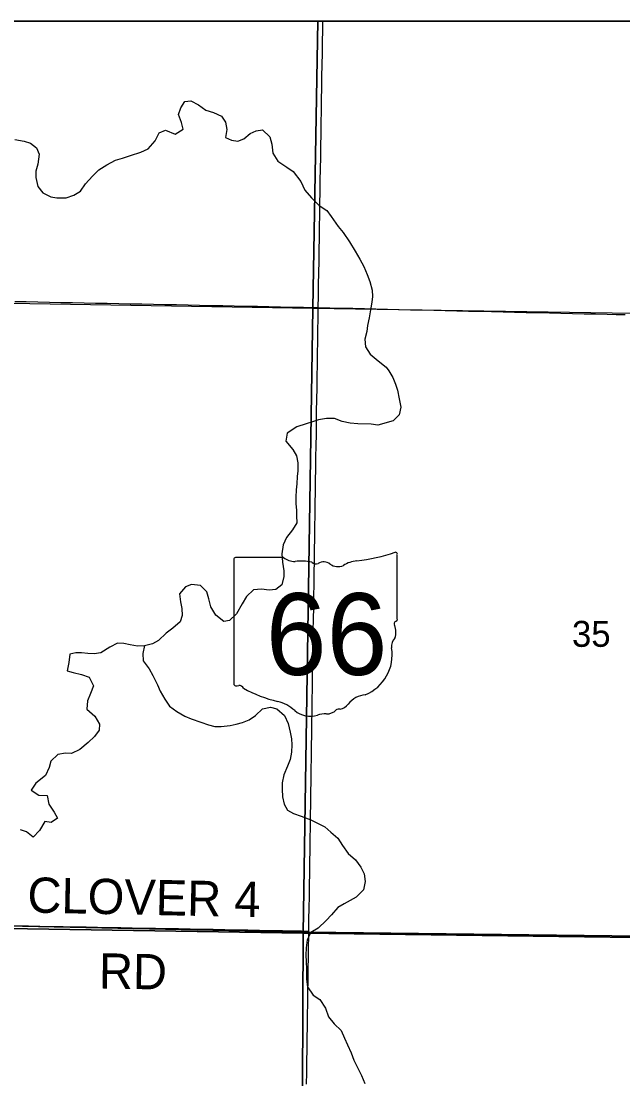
# Model space of a CAD drawing. Extents: x 0 to 34, y 0 to 22.
# Drawn here: x 5.346 to 6.316, y 19.194 to 20.9 of the extents above; entities that cross this region are included whole.
import ezdxf

# ---------------------------------------------------------------- set-up
doc = ezdxf.new("R2010")
doc.units = 0
for name, color, linetype in [('GM_X_Corporation', 7, 'Continuous'), ('GM_X_Minor_River', 7, 'Continuous'), ('GM_X_Section_Text', 7, 'Continuous'), ('GM_X_State_Location', 7, 'Continuous'), ('GM_X_State_Route', 7, 'Continuous'), ('GM_X_State_Shield', 7, 'Continuous'), ('GM_X_Township_Road', 7, 'Continuous'), ('GM_X_Township_Road_Text', 7, 'Continuous'), ('SH_Data', 7, 'Continuous')]:
    doc.layers.add(name, color=color, linetype=linetype)

msp = doc.modelspace()

# ---------------------------------------------------------------- linework, layer by layer
at = {"layer": 'GM_X_Corporation'}
for points in [[(8.9, 20.9), (2.1, 20.9)], [(7.8362, 20.9), (2.1, 20.9)], [(4.7562, 19.4505), (4.8049, 19.4497), (5.2195, 19.4431), (5.8089, 19.4308), (6.6989, 19.42)], [(7.8062, 19.1933), (7.8077, 19.2659), (7.8087, 19.3138), (7.8096, 19.3604), (7.8106, 19.4031), (6.935, 19.4163), (6.733, 19.4196), (6.6989, 19.42), (5.8089, 19.4308), (5.2195, 19.4431), (4.8049, 19.4497), (4.7562, 19.4505)]]:
    msp.add_lwpolyline(points, dxfattribs=at)
for points in [[(5.8246, 20.9), (4.8158, 20.9), (4.8057, 20.4539), (5.8161, 20.437)], [(6.8262, 20.9), (5.8246, 20.9), (5.8161, 20.437), (6.817, 20.4215)], [(4.8057, 20.4539), (5.8161, 20.437), (5.8008, 19.4289), (4.8082, 19.4446), (4.7881, 19.4457)], [(5.8161, 20.437), (6.817, 20.4215), (6.7967, 19.4154), (6.7907, 19.4159), (5.8008, 19.4289)], [(5.8008, 19.4289), (5.7966, 18.4409), (4.7982, 18.4503), (4.8082, 19.4446)], [(5.8008, 19.4289), (6.7907, 19.4159), (6.7843, 18.4413), (5.7966, 18.4409)]]:
    msp.add_lwpolyline(points, close=True, dxfattribs=at)
at = {"layer": 'GM_X_Minor_River'}
for points in [[(5.3359, 20.7091), (5.3506, 20.7065), (5.3612, 20.7032), (5.3709, 20.6957), (5.3748, 20.6854), (5.3726, 20.6695), (5.3696, 20.6578), (5.3694, 20.6479), (5.3729, 20.6334), (5.381, 20.6233), (5.3937, 20.6166), (5.4036, 20.6152), (5.4187, 20.6152), (5.431, 20.6191), (5.4414, 20.6257), (5.4496, 20.6377), (5.4609, 20.65), (5.471, 20.6604), (5.4841, 20.6684), (5.4979, 20.6757), (5.5093, 20.6792), (5.522, 20.6831), (5.5388, 20.6888), (5.551, 20.6938), (5.562, 20.7072), (5.5683, 20.7196), (5.5787, 20.7243), (5.5941, 20.7179), (5.6071, 20.7259), (5.6043, 20.7363), (5.5997, 20.7493), (5.6037, 20.7602), (5.61, 20.7703), (5.6196, 20.7716), (5.6319, 20.7652), (5.6439, 20.7562), (5.6559, 20.7529), (5.6691, 20.7469), (5.6757, 20.7373), (5.6777, 20.7251), (5.6755, 20.7122), (5.6853, 20.7078), (5.6951, 20.7064), (5.705, 20.7104), (5.7151, 20.7189), (5.7247, 20.7232), (5.7349, 20.7245)], [(5.7349, 20.7245), (5.7472, 20.7132), (5.75, 20.7017), (5.7519, 20.6869), (5.76, 20.6742), (5.7742, 20.6643), (5.7846, 20.6573), (5.7968, 20.6414), (5.8033, 20.6272), (5.8144, 20.6148), (5.8266, 20.6027), (5.839, 20.5945), (5.846, 20.5848), (5.8574, 20.569), (5.8651, 20.5593), (5.8754, 20.5443), (5.8845, 20.5292), (5.8922, 20.5161), (5.8984, 20.5042), (5.9038, 20.4912), (5.9081, 20.4801), (5.9119, 20.4659), (5.9125, 20.456), (5.9115, 20.4466), (5.9093, 20.4341), (5.9071, 20.4212), (5.9046, 20.4091), (5.9032, 20.3993), (5.9003, 20.3872), (5.9015, 20.3746), (5.9088, 20.3631), (5.9215, 20.3522), (5.9345, 20.342)], [(5.9345, 20.342), (5.9387, 20.3358), (5.9453, 20.325), (5.9495, 20.3146), (5.9531, 20.3047), (5.9557, 20.2909), (5.958, 20.2772), (5.9554, 20.2652), (5.9461, 20.2555)], [(5.9461, 20.2555), (5.9214, 20.2485), (5.9104, 20.2499), (5.8888, 20.2504), (5.8767, 20.2514), (5.8635, 20.2544), (5.8511, 20.2592), (5.8386, 20.2591), (5.8252, 20.2568), (5.8157, 20.2536), (5.8054, 20.2504), (5.7905, 20.2454), (5.7747, 20.2355), (5.7729, 20.2227), (5.7843, 20.2091), (5.7902, 20.1987), (5.7922, 20.1877), (5.7919, 20.1748), (5.7913, 20.1653), (5.7903, 20.1535), (5.7893, 20.1441), (5.7887, 20.1323), (5.7888, 20.1213), (5.7901, 20.1114), (5.7902, 20.1019), (5.7904, 20.0909), (5.7837, 20.0796), (5.7739, 20.0673), (5.7683, 20.0553), (5.7665, 20.0409), (5.7673, 20.0272), (5.7693, 20.0135), (5.7698, 20.004), (5.7661, 19.9908), (5.7564, 19.983), (5.7458, 19.9821), (5.7337, 19.9839), (5.7204, 19.9827), (5.7092, 19.972), (5.7024, 19.96), (5.6933, 19.9442), (5.6821, 19.9331), (5.6726, 19.9318), (5.6599, 19.942), (5.6519, 19.9555), (5.6488, 19.9684), (5.6452, 19.9795), (5.6352, 19.9897), (5.6208, 19.9911), (5.6109, 19.9876), (5.6015, 19.9764), (5.6031, 19.9634), (5.6051, 19.9524), (5.6057, 19.9413), (5.6024, 19.9312), (5.5904, 19.9208), (5.5796, 19.9127), (5.5672, 19.9008), (5.5576, 19.8954), (5.5446, 19.8926), (5.5336, 19.8921), (5.5215, 19.8939), (5.5113, 19.8961), (5.5015, 19.8967), (5.4888, 19.8905), (5.4745, 19.881), (5.4639, 19.8793), (5.4533, 19.8799), (5.4434, 19.8809), (5.434, 19.8811), (5.4244, 19.8791), (5.4226, 19.8655), (5.42, 19.8518), (5.4298, 19.8493), (5.443, 19.8464), (5.4555, 19.8419), (5.4627, 19.8281), (5.4579, 19.8156), (5.4531, 19.8036), (5.4516, 19.79), (5.4646, 19.7787), (5.4723, 19.7659), (5.4717, 19.7561), (5.4643, 19.746), (5.4542, 19.7364), (5.4407, 19.7253), (5.4272, 19.7188), (5.4174, 19.719), (5.4048, 19.717), (5.394, 19.7062), (5.3911, 19.696), (5.3851, 19.6833), (5.3696, 19.6711), (5.3622, 19.6595), (5.3745, 19.6516), (5.3878, 19.6509), (5.3905, 19.6372), (5.3993, 19.6241), (5.4044, 19.6145), (5.3944, 19.6075), (5.3842, 19.6088)], [(5.5447, 19.8927), (5.5424, 19.8801), (5.5425, 19.8684), (5.5521, 19.8552), (5.5583, 19.8448), (5.5659, 19.8295), (5.5699, 19.8195), (5.5779, 19.8064), (5.5853, 19.7952), (5.5972, 19.7862), (5.6099, 19.7787), (5.6201, 19.7747), (5.6359, 19.769), (5.6483, 19.7649), (5.6581, 19.7624), (5.6687, 19.7625), (5.6832, 19.7637), (5.6927, 19.7658), (5.703, 19.7686), (5.7138, 19.7732), (5.7238, 19.7802), (5.735, 19.791), (5.7483, 19.7933), (5.7582, 19.7908), (5.7708, 19.7799), (5.7766, 19.7672), (5.7797, 19.7531), (5.7821, 19.7424), (5.7826, 19.7329), (5.782, 19.7208), (5.7798, 19.709), (5.7754, 19.6981), (5.7698, 19.6842), (5.7668, 19.6714), (5.767, 19.6611), (5.7675, 19.6489), (5.7702, 19.6371), (5.7757, 19.6275), (5.7854, 19.6219), (5.7975, 19.6175), (5.8133, 19.6118), (5.823, 19.607), (5.8358, 19.6003), (5.8455, 19.5921), (5.8566, 19.5823), (5.8643, 19.5704), (5.8735, 19.5576), (5.8854, 19.5471), (5.8939, 19.5355), (5.8989, 19.5244), (5.9005, 19.5122), (5.898, 19.4989), (5.8863, 19.487), (5.8767, 19.4816), (5.8667, 19.4765), (5.8567, 19.4703), (5.8466, 19.4587), (5.8377, 19.4491), (5.8249, 19.4368), (5.8133, 19.4299), (5.807, 19.4179), (5.8056, 19.405), (5.8053, 19.3936), (5.8054, 19.3833), (5.8059, 19.3704), (5.8059, 19.3548), (5.8076, 19.3426), (5.8167, 19.3291), (5.8276, 19.3217), (5.8367, 19.3078), (5.8417, 19.294), (5.851, 19.2828), (5.8621, 19.2719), (5.8675, 19.2596), (5.8722, 19.2488), (5.8784, 19.2358), (5.8823, 19.2243), (5.8884, 19.2124), (5.8946, 19.1993), (5.9004, 19.1863)], [(5.3842, 19.6088), (5.3755, 19.5946), (5.3654, 19.5838), (5.3546, 19.5924), (5.3448, 19.5957)]]:
    msp.add_lwpolyline(points, dxfattribs=at)
at = {"layer": 'GM_X_State_Route'}
for points in [[(5.8099, 19.4323), (5.8101, 19.4509), (5.8104, 19.4696), (5.8107, 19.4882), (5.811, 19.5069), (5.8113, 19.5255), (5.8115, 19.5441), (5.8118, 19.5628), (5.8121, 19.5814), (5.8124, 19.6001), (5.8127, 19.6187), (5.8129, 19.6374), (5.8132, 19.656), (5.8135, 19.6746), (5.8138, 19.6933), (5.8141, 19.7119), (5.8143, 19.7306), (5.8146, 19.7492), (5.8149, 19.7678), (5.8152, 19.7865), (5.8155, 19.8051), (5.8157, 19.8238), (5.816, 19.8424), (5.8163, 19.861), (5.8166, 19.8797), (5.8169, 19.8983), (5.8171, 19.917), (5.8174, 19.9356), (5.8177, 19.9543), (5.818, 19.9729), (5.8183, 19.9915), (5.8186, 20.0102), (5.8188, 20.0288), (5.8191, 20.0475), (5.8194, 20.0661), (5.8197, 20.0847), (5.82, 20.1034), (5.8203, 20.122), (5.8205, 20.1407), (5.8208, 20.1593), (5.8211, 20.1779), (5.8214, 20.1966), (5.8217, 20.2152), (5.822, 20.2339), (5.8222, 20.2525), (5.8225, 20.2711), (5.8228, 20.2898), (5.8231, 20.3084), (5.8234, 20.3271), (5.8236, 20.3457), (5.8239, 20.3644), (5.8242, 20.383), (5.8245, 20.4016), (5.8248, 20.4199), (5.8251, 20.4381), (5.8254, 20.4567), (5.8257, 20.4754), (5.826, 20.494), (5.8263, 20.5127), (5.8266, 20.5313), (5.8269, 20.5499), (5.8272, 20.5686), (5.8275, 20.5872), (5.8278, 20.6059), (5.8281, 20.6245), (5.8284, 20.6431), (5.8287, 20.6618), (5.829, 20.6804), (5.8293, 20.6991), (5.8296, 20.7177), (5.8299, 20.7364), (5.8302, 20.755), (5.8305, 20.7736), (5.8308, 20.7923), (5.8311, 20.8109), (5.8314, 20.8296), (5.8317, 20.8482), (5.832, 20.8668), (5.8323, 20.8855), (5.8326, 20.9)], [(5.8061, 19.1852), (5.8064, 19.2038), (5.8067, 19.2225), (5.807, 19.2411), (5.8073, 19.2598), (5.8075, 19.2784), (5.8078, 19.297), (5.8081, 19.3157), (5.8084, 19.3343), (5.8087, 19.353), (5.8089, 19.3716), (5.8092, 19.3902), (5.8095, 19.4089), (5.8097, 19.4206), (5.8099, 19.4323)]]:
    msp.add_lwpolyline(points, dxfattribs=at)
at = {"layer": 'GM_X_State_Shield'}
for p, q in [((5.689, 20.0315), (5.689, 19.8314)), ((5.7688, 20.035), (5.6916, 20.035)), ((5.9526, 19.9352), (5.9526, 20.0399)), ((5.9526, 19.9353), (5.9526, 19.9352))]:
    msp.add_line(p, q, dxfattribs=at)
for centre, radius, start, end in [((5.692, 20.0319), 0.00305, 98.1301, 188.1301), ((5.7872, 20.0582), 0.0296, 231.6195, 271.1119), ((5.8944, 19.9738), 0.0563, 97.3462, 120.7689), ((5.8587, 20.3078), 0.2796, 275.8445, 288.9065), ((5.9497, 20.0404), 0.00294, 351.8621, 97.738), ((5.797, 19.9226), 0.1064, 80.4867, 94.9883), ((5.8211, 20.033), 0.00855, 219.7921, 297.1024), ((5.8337, 20.0099), 0.0178, 54.4667, 119.1411), ((5.8566, 20.0416), 0.0214, 233.8562, 294.8282), ((5.9519, 19.9276), 0.00454, 107.944, 210.337), ((5.9495, 19.9348), 0.00314, 289.6038, 7.7341), ((5.923, 19.9143), 0.0273, 340.033, 23.6496), ((5.9631, 19.8914), 0.0198, 136.8065, 186.9296), ((5.8744, 19.8781), 0.0699, 292.3089, 8.9858), ((5.692, 19.831), 0.00308, 171.9584, 258.3066), ((5.6925, 19.8514), 0.0235, 267.339, 280.6039), ((5.6973, 19.8199), 0.00848, 29.7484, 93.2717), ((5.8043, 19.9997), 0.2019, 240.4129, 257.1985), ((5.9039, 19.7752), 0.0383, 94.4031, 142.5768), ((5.7441, 19.7415), 0.0632, 47.1842, 75.836), ((5.8579, 19.7845), 0.00601, 65.7517, 132.6484), ((5.8553, 19.812), 0.0226, 282.8732, 323.2771), ((5.8125, 19.8189), 0.0401, 230.7004, 286.2918), ((5.8356, 19.7497), 0.0329, 85.6951, 111.2099), ((5.8386, 19.8039), 0.0214, 268.777, 315.5493)]:
    msp.add_arc(centre, radius, start, end, dxfattribs=at)
at = {"layer": 'GM_X_Township_Road'}
for points in [[(5.3356, 20.4479), (5.3542, 20.4476), (5.3729, 20.4472), (5.3915, 20.4468), (5.4101, 20.4464), (5.4288, 20.4461), (5.4474, 20.4457), (5.466, 20.4453), (5.4847, 20.445), (5.5033, 20.4446), (5.5219, 20.4442), (5.5406, 20.4438), (5.5592, 20.4435), (5.5778, 20.4431), (5.5965, 20.4427), (5.6151, 20.4423), (5.6338, 20.442), (5.6524, 20.4416), (5.671, 20.4412), (5.6897, 20.4408), (5.7083, 20.4404), (5.7269, 20.4401), (5.7456, 20.4397), (5.7642, 20.4393), (5.7828, 20.4389), (5.8015, 20.4386), (5.8133, 20.4383), (5.8251, 20.4381)], [(5.8251, 20.4381), (5.8437, 20.4377), (5.8623, 20.4372), (5.881, 20.4368), (5.8996, 20.4364), (5.9182, 20.4359), (5.9369, 20.4355), (5.9555, 20.435), (5.9741, 20.4346), (5.9928, 20.4342), (6.0114, 20.4337), (6.03, 20.4333), (6.0487, 20.4329), (6.0673, 20.4324), (6.0859, 20.432), (6.1046, 20.4316), (6.1232, 20.4311), (6.1418, 20.4307), (6.1605, 20.4303), (6.1791, 20.4298), (6.1978, 20.4294), (6.2164, 20.429), (6.235, 20.4285), (6.2537, 20.4281), (6.2723, 20.4277), (6.2909, 20.4272), (6.3054, 20.4269), (6.3198, 20.4266)], [(5.3388, 19.441), (5.3575, 19.4406), (5.3761, 19.4403), (5.3947, 19.4399), (5.4134, 19.4396), (5.432, 19.4393), (5.4506, 19.4389), (5.4693, 19.4386), (5.4879, 19.4382), (5.5065, 19.4379), (5.5252, 19.4376), (5.5438, 19.4372), (5.5624, 19.4369), (5.5811, 19.4365), (5.5997, 19.4362), (5.6184, 19.4358), (5.637, 19.4355), (5.6556, 19.4352), (5.6743, 19.4348), (5.6929, 19.4345), (5.7115, 19.4341), (5.7302, 19.4338), (5.7488, 19.4334), (5.7674, 19.4331), (5.7861, 19.4327), (5.798, 19.4325), (5.8099, 19.4323)]]:
    msp.add_lwpolyline(points, dxfattribs=at)
at = {"layer": 'SH_Data'}
msp.add_line((2.1, 20.9), (8.9, 20.9), dxfattribs=at)
msp.add_line((2.1, 20.9), (8.9, 20.9), dxfattribs=at)

# ---------------------------------------------------------------- texts
at = {"layer": 'GM_X_Section_Text'}
msp.add_text('35', height=0.04186, rotation=0, dxfattribs=at).set_placement((6.2343, 19.8908))
at = {"layer": 'GM_X_State_Location'}
for s in ['s', 'r']:
    msp.add_text(s, height=0.000189, dxfattribs=at).set_placement((5.8178, 19.9182))
msp.add_text('66', height=0.000189, rotation=0, dxfattribs=at).set_placement((5.7701, 19.9044))
at = {"layer": 'GM_X_State_Shield'}
msp.add_text('66', height=0.13184, dxfattribs=at).set_placement((5.7405, 19.8455))
at = {"layer": 'GM_X_Township_Road_Text'}
for s, rotation, p in [('CLOVER 4', 358.8428, (5.3556, 19.4623)), ('RD', 359.0118, (5.4709, 19.3398))]:
    msp.add_text(s, height=0.05682, rotation=rotation, dxfattribs=at).set_placement(p)

doc.saveas('drawing.dxf')
